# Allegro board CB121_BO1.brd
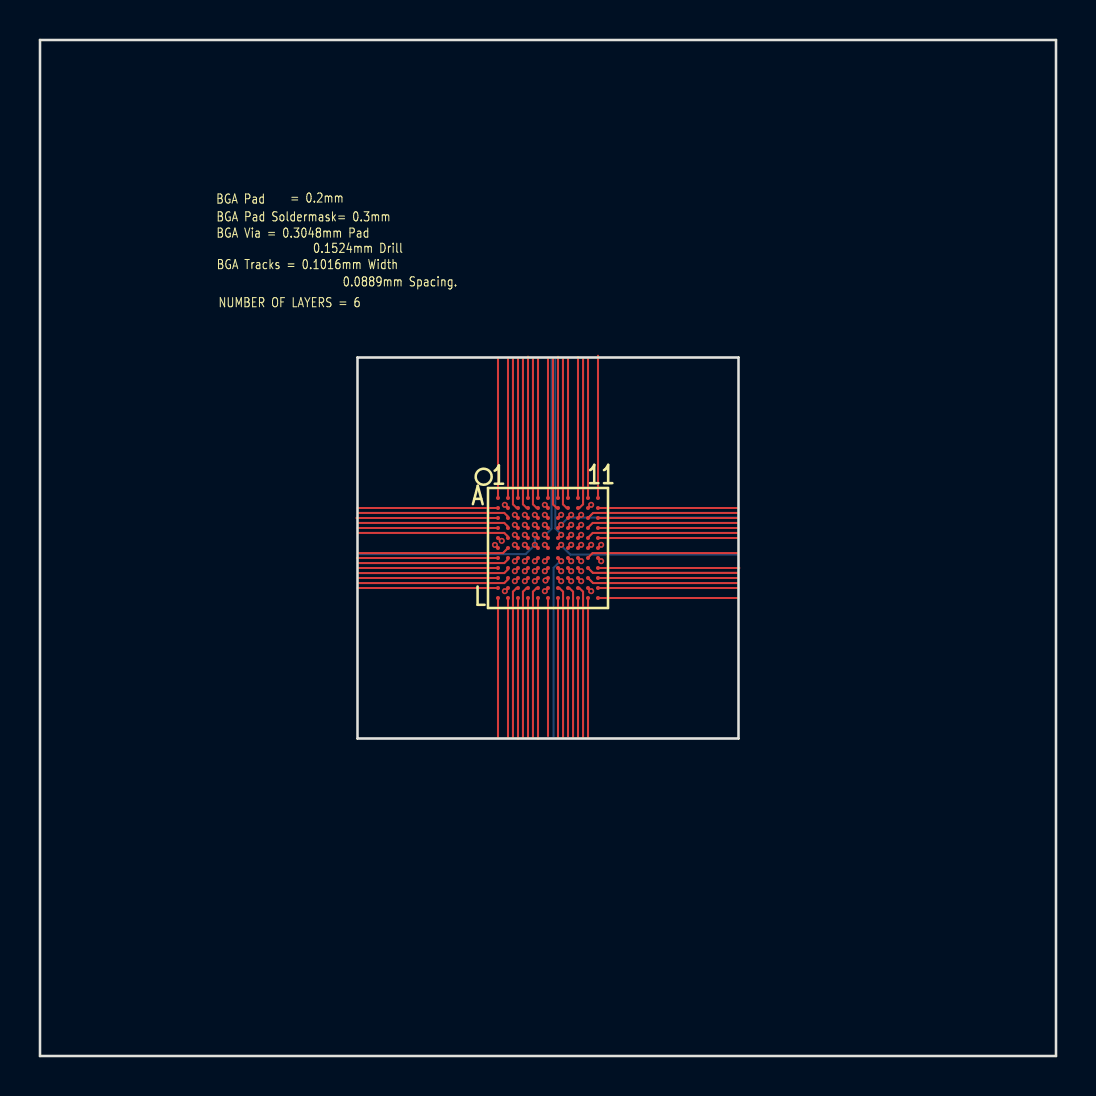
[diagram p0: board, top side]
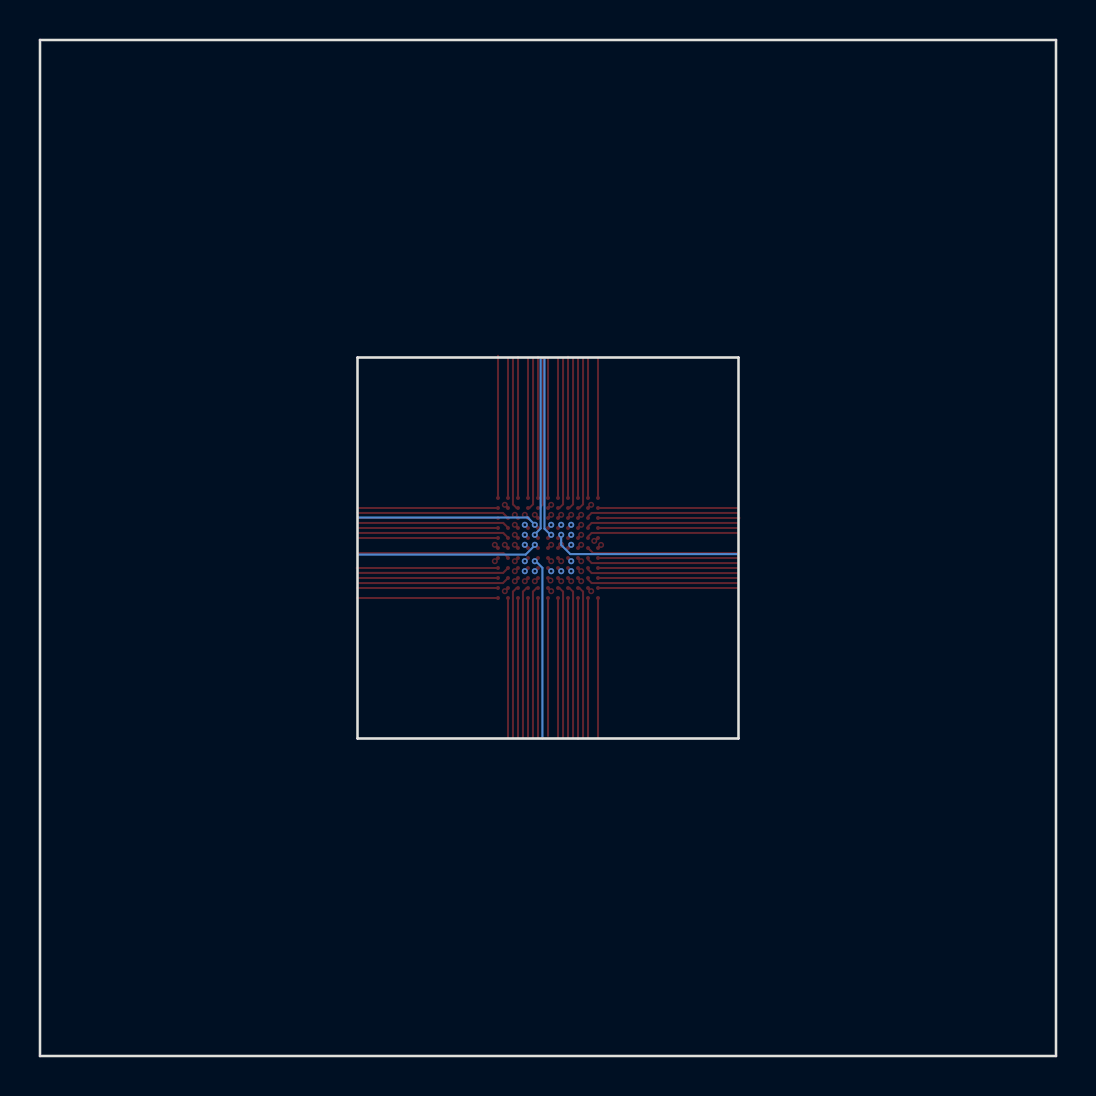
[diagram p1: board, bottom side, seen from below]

Outline 50.8 x 50.8 mm; copper layers: TOP, GND, SIGNAL1, SIGNAL2, POWER, BOTTOM. Coordinates in mm from the lower left corner of the outline.
Outline path: 0,50.8 0,0 50.8,0 50.8,50.8 0,50.8 ; 15.87,34.92 15.87,15.87 34.92,15.87 34.92,34.92 15.87,34.92

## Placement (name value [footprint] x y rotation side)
U1  -  [BGA11X11-121_0-2MM]  25.4 25.4 0 top

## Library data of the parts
U1 = BGA11X11-121_0-2MM

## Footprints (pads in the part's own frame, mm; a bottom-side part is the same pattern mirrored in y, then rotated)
BGA11X11-121_0-2MM
  round 0.2 smd: A1(-2.5,2.5) A2(-2,2.5) A3(-1.5,2.5) A4(-1,2.5) A5(-0.5,2.5) A6(0,2.5) A7(0.5,2.5) A8(1,2.5) A9(1.5,2.5) A10(2,2.5) A11(2.5,2.5) B1(-2.5,2) B2(-2,2) B3(-1.5,2) B4(-1,2) B5(-0.5,2) B6(0,2) B7(0.5,2) B8(1,2) B9(1.5,2) B10(2,2) B11(2.5,2) C1(-2.5,1.5) C2(-2,1.5) C3(-1.5,1.5) C4(-1,1.5) C5(-0.5,1.5) C6(0,1.5) C7(0.5,1.5) C8(1,1.5) C9(1.5,1.5) C10(2,1.5) C11(2.5,1.5) D1(-2.5,1) D2(-2,1) D3(-1.5,1) D4(-1,1) D5(-0.5,1) D6(0,1) D7(0.5,1) D8(1,1) D9(1.5,1) D10(2,1) D11(2.5,1) E1(-2.5,0.5) E2(-2,0.5) E3(-1.5,0.5) E4(-1,0.5) E5(-0.5,0.5) E6(0,0.5) E7(0.5,0.5) E8(1,0.5) E9(1.5,0.5) E10(2,0.5) E11(2.5,0.5) F1(-2.5,0) F2(-2,0) F3(-1.5,0) F4(-1,0) F5(-0.5,0) F6(0,0) F7(0.5,0) F8(1,0) F9(1.5,0) F10(2,0) F11(2.5,0) G1(-2.5,-0.5) G2(-2,-0.5) G3(-1.5,-0.5) G4(-1,-0.5) G5(-0.5,-0.5) G6(0,-0.5) G7(0.5,-0.5) G8(1,-0.5) G9(1.5,-0.5) G10(2,-0.5) G11(2.5,-0.5) H1(-2.5,-1) H2(-2,-1) H3(-1.5,-1) H4(-1,-1) H5(-0.5,-1) H6(0,-1) H7(0.5,-1) H8(1,-1) H9(1.5,-1) H10(2,-1) H11(2.5,-1) J1(-2.5,-1.5) J2(-2,-1.5) J3(-1.5,-1.5) J4(-1,-1.5) J5(-0.5,-1.5) J6(0,-1.5) J7(0.5,-1.5) J8(1,-1.5) J9(1.5,-1.5) J10(2,-1.5) J11(2.5,-1.5) K1(-2.5,-2) K2(-2,-2) K3(-1.5,-2) K4(-1,-2) K5(-0.5,-2) K6(0,-2) K7(0.5,-2) K8(1,-2) K9(1.5,-2) K10(2,-2) K11(2.5,-2) L1(-2.5,-2.5) L2(-2,-2.5) L3(-1.5,-2.5) L4(-1,-2.5) L5(-0.5,-2.5) L6(0,-2.5) L7(0.5,-2.5) L8(1,-2.5) L9(1.5,-2.5) L10(2,-2.5) L11(2.5,-2.5)

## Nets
GND: U1.B2 U1.B10 U1.E1 U1.F5 U1.F6 U1.G5 U1.G6 U1.G11 U1.K2 U1.K10
VCC: U1.B6 U1.F1 U1.F11 U1.K6
A1: U1.A1
A2: U1.A2
A3: U1.A3
A4: U1.A4
A5: U1.A5
A6: U1.A6
A7: U1.A7
A8: U1.A8
A10: U1.A10
A11: U1.A11
B1: U1.B1
B3: U1.B3
B4: U1.B4
B5: U1.B5
B7: U1.B7
B8: U1.B8
B9: U1.B9
B11: U1.B11
C1: U1.C1
C2: U1.C2
C3: U1.C3
C4: U1.C4
C5: U1.C5
C6: U1.C6
C7: U1.C7
C8: U1.C8
C9: U1.C9
C11: U1.C11
D1: U1.D1
D2: U1.D2
D3: U1.D3
D4: U1.D4
D5: U1.D5
D6: U1.D6
D7: U1.D7
D8: U1.D8
D9: U1.D9
D10: U1.D10
D11: U1.D11
E2: U1.E2
E3: U1.E3
E4: U1.E4
E5: U1.E5
E6: U1.E6
E7: U1.E7
E8: U1.E8
E9: U1.E9
E10: U1.E10
E11: U1.E11
F2: U1.F2
F3: U1.F3
F4: U1.F4
F7: U1.F7
F8: U1.F8
F9: U1.F9
F10: U1.F10
G1: U1.G1
G2: U1.G2
G3: U1.G3
G4: U1.G4
G7: U1.G7
G8: U1.G8
G9: U1.G9
G10: U1.G10
H1: U1.H1
H2: U1.H2
H3: U1.H3
H4: U1.H4
H5: U1.H5
H6: U1.H6
H7: U1.H7
H8: U1.H8
H9: U1.H9
H10: U1.H10
H11: U1.H11
J1: U1.J1
J2: U1.J2
J3: U1.J3
J4: U1.J4
J5: U1.J5
J6: U1.J6
J7: U1.J7
J8: U1.J8
J9: U1.J9
J10: U1.J10
J11: U1.J11
K1: U1.K1
K3: U1.K3
K4: U1.K4
K5: U1.K5
K7: U1.K7
K8: U1.K8
K9: U1.K9
K11: U1.K11
L1: U1.L1
L2: U1.L2
L3: U1.L3
L4: U1.L4
L5: U1.L5
L6: U1.L6
L7: U1.L7
L8: U1.L8
L9: U1.L9
L10: U1.L10
L11: U1.L11
VPP_2V5: U1.C10
VPP_FAST: U1.A9

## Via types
v1: diameter 0.305, hole 0.152, TOP to SIGNAL1, 25 vias
v2: diameter 0.305, hole 0.152, TOP to BOTTOM, 21 vias
v3: diameter 0.305, hole 0.152, TOP to POWER, 4 vias
v4: diameter 0.305, hole 0.152, TOP to GND, 10 vias

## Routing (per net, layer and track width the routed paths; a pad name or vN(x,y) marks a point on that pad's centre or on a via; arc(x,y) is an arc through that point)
GND: length 2.3
  TOP w0.102: v4(23.24,23.24) U1.K2 ; v4(25.24,24.74) U1.G6 ; v4(27.56,23.24) U1.K10 ; U1.E1 23.04,25.76 v4(23.09,25.76) ; v4(24.74,25.56) U1.F5 ; v4(28.06,24.74) U1.G11 ; v4(23.24,27.56) U1.B2 ; v4(27.56,27.56) U1.B10 ; v4(24.74,24.74) U1.G5 ; v4(25.24,25.56) U1.F6
VCC: length 0.9
  TOP w0.102: v3(25.24,23.24) U1.K6 ; v3(22.75,25.55) U1.F1 ; v3(28.06,25.56) U1.F11 ; v3(25.24,27.56) U1.B6
A1: length 7
  TOP w0.102: U1.A1 22.9,34.91
A2: length 7
  TOP w0.102: U1.A2 23.4,34.92
A3: length 7
  TOP w0.102: U1.A3 23.9,34.9
A4: length 7.1
  TOP w0.102: U1.A4 24.4,34.97
A5: length 7
  TOP w0.102: U1.A5 24.9,34.91
A6: length 7
  TOP w0.102: U1.A6 25.4,34.92
A7: length 7.1
  TOP w0.102: U1.A7 25.9,34.96
A8: length 7
  TOP w0.102: U1.A8 26.4,34.91
A10: length 7
  TOP w0.102: U1.A10 27.4,34.89
A11: length 7.1
  TOP w0.102: U1.A11 27.9,35.01
B1: length 7
  TOP w0.102: U1.B1 15.88,27.4
B3: length 7.6
  TOP w0.102: U1.B3 23.83,27.4 23.65,27.58 23.65,34.87
B4: length 7.6
  TOP w0.102: 24.15,34.87 24.15,27.58 24.33,27.4 U1.B4
B5: length 7.6
  TOP w0.102: 24.65,34.87 24.65,27.58 24.83,27.4 U1.B5
B7: length 7.6
  TOP w0.102: U1.B7 25.83,27.4 25.65,27.58 25.65,34.87
B8: length 7.6
  TOP w0.102: 26.15,34.87 26.15,27.58 26.33,27.4 U1.B8
B9: length 7.6
  TOP w0.102: 27.15,34.87 27.15,27.58 26.97,27.4 U1.B9
B11: length 7
  TOP w0.102: U1.B11 34.92,27.4
C1: length 7.1
  TOP w0.102: U1.C1 15.83,26.9
C2: length 7.6
  TOP w0.102: U1.C2 23.4,26.97 23.22,27.15 15.93,27.15
C3: length 8.1
  TOP w0.102: v1(23.74,27.06) U1.C3
  SIGNAL1 w0.102: v1(23.74,27.06) 15.89,27.06
C4: length 8.1
  TOP w0.102: v1(24.24,27.06) U1.C4
  SIGNAL1 w0.102: v1(24.24,27.06) 24.24,34.91
C5: length 8.1
  TOP w0.102: v1(24.74,27.06) U1.C5
  SIGNAL1 w0.102: v1(24.74,27.06) 24.74,34.91
C6: length 8.2
  TOP w0.102: v1(25.24,27.06) U1.C6
  SIGNAL1 w0.102: 25.55,34.91 25.55,27.37 v1(25.24,27.06)
C7: length 8.1
  TOP w0.102: v1(26.06,27.06) U1.C7
  SIGNAL1 w0.102: v1(26.06,27.06) 26.06,34.91
C8: length 8.1
  TOP w0.102: v1(26.56,27.06) U1.C8
  SIGNAL1 w0.102: v1(26.56,27.06) 26.56,34.91
C9: length 8.1
  TOP w0.102: v1(27.06,27.06) U1.C9
  SIGNAL1 w0.102: v1(27.06,27.06) 34.91,27.06
C11: length 7
  TOP w0.102: U1.C11 34.9,26.9
D1: length 7
  TOP w0.102: U1.D1 15.88,26.4
D2: length 7.6
  TOP w0.102: U1.D2 23.4,26.47 23.22,26.65 15.93,26.65
D3: length 8.1
  TOP w0.102: v1(23.74,26.56) U1.D3
  SIGNAL1 w0.102: v1(23.74,26.56) 15.89,26.56
D4: length 8.5
  TOP w0.102: v2(24.24,26.56) U1.D4
  SIGNAL2 w0.102: v2(24.24,26.56) 15.92,26.56
D5: length 8.5
  TOP w0.102: v2(24.74,26.56) U1.D5
  SIGNAL2 w0.102: v2(24.74,26.56) 24.74,34.87
D6: length 8.7
  TOP w0.102: v2(25.24,26.56) U1.D6
  SIGNAL2 w0.102: 25.53,34.87 25.53,27.69 25.53,27.68 25.53,27.44 25.53,27.43 25.53,26.85 v2(25.24,26.56)
D7: length 9.2
  TOP w0.102: v2(26.06,26.56) U1.D7
  BOTTOM w0.102: 34.9,26.92 26.42,26.92 26.06,26.57 v2(26.06,26.56)
D8: length 8.5
  TOP w0.102: v2(26.56,26.56) U1.D8
  SIGNAL2 w0.102: v2(26.56,26.56) 34.87,26.56
D9: length 8.1
  TOP w0.102: v1(27.06,26.56) U1.D9
  SIGNAL1 w0.102: v1(27.06,26.56) 34.91,26.56
D10: length 7.6
  TOP w0.102: U1.D10 27.4,26.42 27.64,26.65 34.87,26.65
D11: length 7
  TOP w0.102: U1.D11 34.92,26.4
E2: length 7.6
  TOP w0.102: U1.E2 23.4,25.97 23.22,26.15 15.93,26.15
E3: length 8.1
  TOP w0.102: v1(23.74,26.06) U1.E3
  SIGNAL1 w0.102: v1(23.74,26.06) 15.89,26.06
E4: length 8.5
  TOP w0.102: v2(24.24,26.06) U1.E4
  SIGNAL2 w0.102: v2(24.24,26.06) 15.93,26.06
E5: length 9.8
  TOP w0.102: v2(24.74,26.06) U1.E5
  BOTTOM w0.102: 15.9,25.1 24.28,25.1 24.74,25.55 v2(24.74,26.06)
E6: length 9.2
  TOP w0.102: v2(25.24,26.06) U1.E6
  BOTTOM w0.102: v2(25.24,26.06) 25.27,26.06 25.58,26.36 25.58,34.9
E7: length 9.1
  TOP w0.102: v2(26.06,26.06) U1.E7
  BOTTOM w0.102: 25.77,34.83 25.77,26.38 26.06,26.09 v2(26.06,26.06)
E8: length 8.5
  TOP w0.102: v2(26.56,26.06) U1.E8
  SIGNAL2 w0.102: v2(26.56,26.06) 34.87,26.06
E9: length 8.1
  TOP w0.102: v1(27.06,26.06) U1.E9
  SIGNAL1 w0.102: v1(27.06,26.06) 34.91,26.06
E10: length 7.6
  TOP w0.102: U1.E10 27.4,25.92 27.64,26.15 34.87,26.15
E11: length 7
  TOP w0.102: U1.E11 34.88,25.9
F2: length 7.6
  TOP w0.102: U1.F2 23.15,25.15 15.93,25.15
F3: length 8.2
  TOP w0.102: v1(23.74,25.56) U1.F3
  SIGNAL1 w0.102: 15.89,25.87 23.43,25.87 v1(23.74,25.56)
F4: length 8.7
  TOP w0.102: v2(24.24,25.56) U1.F4
  SIGNAL2 w0.102: v2(24.24,25.56) 23.83,25.15 15.93,25.15
F7: length 9.3
  TOP w0.102: v2(26.06,25.56) U1.F7
  BOTTOM w0.102: 34.9,25.07 26.52,25.07 26.06,25.53 v2(26.06,25.56)
F8: length 8.7
  TOP w0.102: v2(26.56,25.56) U1.F8
  SIGNAL2 w0.102: 34.87,25.22 26.9,25.22 v2(26.56,25.56)
F9: length 8.2
  TOP w0.102: v1(27.06,25.56) U1.F9
  SIGNAL1 w0.102: v1(27.06,25.56) 27.06,25.54 27.43,25.17 34.9,25.17
F10: length 7.8
  TOP w0.102: v1(27.56,25.56) U1.F10
  SIGNAL1 w0.102: v1(27.56,25.56) 27.87,25.87 34.99,25.87 35.01,25.89
G1: length 7
  TOP w0.102: U1.G1 15.86,24.9
G2: length 7.6
  TOP w0.102: 15.93,24.65 23.22,24.65 23.4,24.83 U1.G2
G3: length 8.1
  TOP w0.102: v1(23.74,24.74) U1.G3
  SIGNAL1 w0.102: v1(23.74,24.74) 15.89,24.74
G4: length 8.5
  TOP w0.102: v2(24.24,24.74) U1.G4
  SIGNAL2 w0.102: v2(24.24,24.74) 15.93,24.74
G7: length 9.3
  TOP w0.102: v2(26.06,24.74) U1.G7
  BOTTOM w0.102: 25.68,15.87 25.68,24.41 26.01,24.74 v2(26.06,24.74)
G8: length 8.5
  TOP w0.102: v2(26.56,24.74) U1.G8
  SIGNAL2 w0.102: v2(26.56,24.74) 34.87,24.74
G9: length 8.1
  TOP w0.102: v1(27.06,24.74) U1.G9
  SIGNAL1 w0.102: v1(27.06,24.74) 34.91,24.74
G10: length 7.6
  TOP w0.102: U1.G10 27.4,24.92 27.63,25.15 34.87,25.15
H1: length 7
  TOP w0.102: U1.H1 15.89,24.4
H2: length 7.6
  TOP w0.102: U1.H2 23.4,24.33 23.22,24.15 15.93,24.15
H3: length 8.1
  TOP w0.102: v1(23.74,24.24) U1.H3
  SIGNAL1 w0.102: v1(23.74,24.24) 15.89,24.24
H4: length 8.5
  TOP w0.102: v2(24.24,24.24) U1.H4
  SIGNAL2 w0.102: v2(24.24,24.24) 15.93,24.24
H5: length 8.5
  TOP w0.102: v2(24.74,24.24) U1.H5
  SIGNAL2 w0.102: v2(24.74,24.24) 24.74,15.93
H6: length 8.7
  TOP w0.102: v2(25.24,24.24) U1.H6
  SIGNAL2 w0.102: v2(25.24,24.24) 25.53,23.95 25.53,15.93
H7: length 8.5
  TOP w0.102: v2(26.06,24.24) U1.H7
  SIGNAL2 w0.102: v2(26.06,24.24) 26.06,15.93
H8: length 8.5
  TOP w0.102: v2(26.56,24.24) U1.H8
  SIGNAL2 w0.102: v2(26.56,24.24) 26.56,15.93
H9: length 8.1
  TOP w0.102: v1(27.06,24.24) U1.H9
  SIGNAL1 w0.102: v1(27.06,24.24) 34.91,24.24
H10: length 7.6
  TOP w0.102: U1.H10 27.64,24.16 34.87,24.16
H11: length 7.1
  TOP w0.102: U1.H11 34.97,24.4
J1: length 7
  TOP w0.102: U1.J1 15.92,23.9
J2: length 7.6
  TOP w0.102: 15.93,23.65 23.22,23.65 23.4,23.83 U1.J2
J3: length 8.1
  TOP w0.102: v1(23.74,23.74) U1.J3
  SIGNAL1 w0.102: v1(23.74,23.74) 15.89,23.74
J4: length 8.1
  TOP w0.102: v1(24.24,23.74) U1.J4
  SIGNAL1 w0.102: v1(24.24,23.74) 24.24,15.89
J5: length 8.1
  TOP w0.102: v1(24.74,23.74) U1.J5
  SIGNAL1 w0.102: v1(24.74,23.74) 24.74,15.89
J6: length 8.2
  TOP w0.102: 25.24,23.74 v1(25.27,23.77) U1.J6
  SIGNAL1 w0.102: 24.94,15.93 24.94,23.44 v1(25.27,23.77)
J7: length 8.1
  TOP w0.102: v1(26.06,23.74) U1.J7
  SIGNAL1 w0.102: v1(26.06,23.74) 26.06,15.89
J8: length 8.1
  TOP w0.102: v1(26.56,23.74) U1.J8
  SIGNAL1 w0.102: v1(26.56,23.74) 26.56,15.89
J9: length 8.1
  TOP w0.102: v1(27.06,23.74) U1.J9
  SIGNAL1 w0.102: v1(27.06,23.74) 27.06,15.89
J10: length 7.6
  TOP w0.102: U1.J10 27.65,23.65 34.87,23.65
J11: length 7
  TOP w0.102: U1.J11 34.88,23.9
K1: length 7
  TOP w0.102: U1.K1 15.88,23.4
K3: length 7.6
  TOP w0.102: 23.65,15.93 23.65,23.22 23.83,23.4 U1.K3
K4: length 7.6
  TOP w0.102: 24.15,15.93 24.15,23.22 24.33,23.4 U1.K4
K5: length 7.6
  TOP w0.102: 24.65,15.93 24.65,23.22 24.83,23.4 U1.K5
K7: length 7.6
  TOP w0.102: 26.15,15.93 26.15,23.22 25.97,23.4 U1.K7
K8: length 7.6
  TOP w0.102: 26.65,15.93 26.65,23.22 26.47,23.4 U1.K8
K9: length 7.6
  TOP w0.102: 27.15,15.93 27.15,23.22 26.97,23.4 U1.K9
K11: length 7
  TOP w0.102: U1.K11 34.93,23.4
L1: length 7
  TOP w0.102: U1.L1 22.9,15.86
L2: length 7
  TOP w0.102: U1.L2 23.4,15.94
L3: length 7.1
  TOP w0.102: U1.L3 23.9,15.85
L4: length 7
  TOP w0.102: U1.L4 24.4,15.89
L5: length 7
  TOP w0.102: U1.L5 24.9,15.86
L6: length 6.9
  TOP w0.102: U1.L6 25.4,16
L7: length 7
  TOP w0.102: U1.L7 25.9,15.93
L8: length 6.9
  TOP w0.102: U1.L8 26.4,15.97
L9: length 6.9
  TOP w0.102: U1.L9 26.9,15.95
L10: length 7
  TOP w0.102: U1.L10 27.4,15.93
L11: length 7
  TOP w0.102: U1.L11 34.94,22.9
VPP_2V5: length 7.6
  TOP w0.102: 34.92,27.15 27.65,27.15 U1.C10
VPP_FAST: length 7
  TOP w0.102: U1.A9 26.9,34.95

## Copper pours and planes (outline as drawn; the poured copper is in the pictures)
GND on GND: 22.61,28.19 22.61,22.61 28.19,22.61 28.19,28.19
VCC on POWER: 22.61,28.19 22.61,22.61 28.19,22.61 28.19,28.19

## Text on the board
Ref Des/Silkscreen Top: BGA Pad | BGA Pad Soldermask= 0.3mm | BGA Via = 0.3048mm Pad | BGA Tracks = 0.1016mm Width | NUMBER OF LAYERS = 6 | = 0.2mm | 0.1524mm Drill | 0.0889mm Spacing.
NCLEGEND-1-2: FIGURE | SIZE | 6.0 | DRILL CHART: TOP to GND | ALL UNITS ARE IN MILS | PLATED | QTY | 10
NCLEGEND-1-3: FIGURE | SIZE | 6.0 | DRILL CHART: TOP to SIGNAL1 | ALL UNITS ARE IN MILS | PLATED | QTY | 25
NCLEGEND-1-5: FIGURE | SIZE | 6.0 | DRILL CHART: TOP to POWER | ALL UNITS ARE IN MILS | PLATED | QTY | 4
NCLEGEND-1-6: FIGURE | SIZE | 6.0 | DRILL CHART: TOP to BOTTOM | ALL UNITS ARE IN MILS | PLATED | QTY | 21
